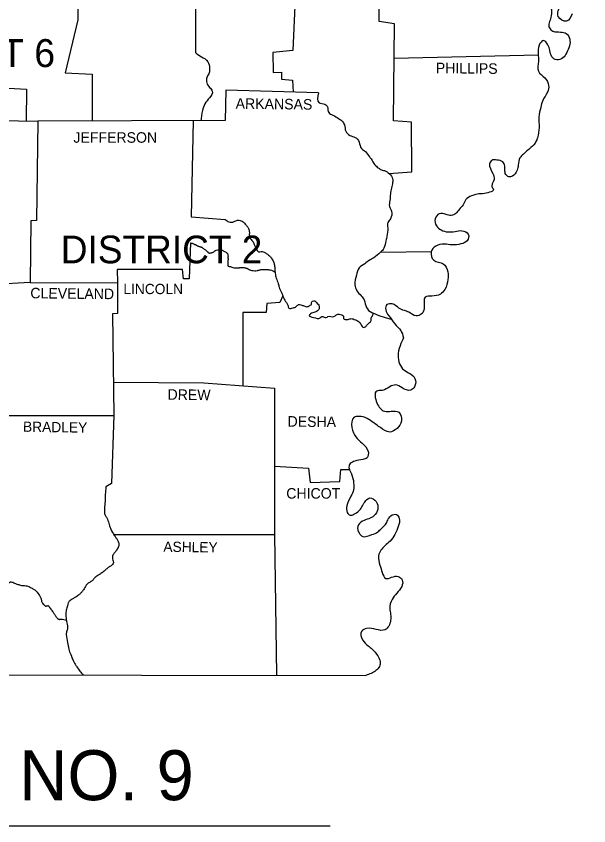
# Model space of a CAD drawing. Extents: x 6028647 to 6035072, y 5366486 to 5368495.
# Drawn here: x 6031362.3 to 6031596, y 5367756.8 to 5368087.3 of the extents above; entities that cross this region are included whole.
import ezdxf

# ---------------------------------------------------------------- set-up
doc = ezdxf.new("R2010")
doc.units = 0
doc.layers.add('Default', color=7, linetype='Continuous')

msp = doc.modelspace()

# ---------------------------------------------------------------- linework, layer by layer
at = {"layer": 'Default'}
for p, q in [((6031511.06, 5367990.98), (6031531.81, 5367991.29)), ((6031157.07, 5367756.79), (6031490.53, 5367756.79))]:
    msp.add_line(p, q, dxfattribs=at)
for points in [[(6031421.06, 5368129.07), (6031421.26, 5368111.17), (6031435.36, 5368110.87), (6031435.46, 5368072.47)], [(6031381.56, 5368124.47), (6031387.36, 5368124.07), (6031387.46, 5368085.87), (6031382.26, 5368064.17), (6031393.36, 5368063.67), (6031393.26, 5368044.56)], [(6031514.44, 5368023.17), (6031523.76, 5368023.77), (6031523.66, 5368044.07), (6031516.36, 5368044.57), (6031516.76, 5368084.27), (6031510.46, 5368085.17), (6031510.26, 5368111.87), (6031596.05, 5368112.47)], [(6031476.46, 5368100.77), (6031475.26, 5368073.37), (6031467.06, 5368072.47), (6031467.26, 5368064.37), (6031470.56, 5368064.47), (6031470.66, 5368061.67), (6031475.16, 5368061.17), (6031475.31, 5368056.35)], [(6031303.67, 5368099.52), (6031315.57, 5368098.77), (6031315.17, 5368086.27), (6031328.27, 5368085.77), (6031328.47, 5368074.87), (6031334.67, 5368074.37), (6031334.67, 5368072.47), (6031340.47, 5368072.07), (6031340.66, 5368065.07), (6031353.86, 5368065.07), (6031354.26, 5368058.17), (6031366.46, 5368057.57), (6031366.36, 5368044.55)], [(6031516.62, 5368070.16), (6031575.38, 5368071.62)], [(6031485.66, 5368056.07), (6031447.86, 5368057.07), (6031447.66, 5368044.77), (6031371.17, 5368044.47)], [(6031313.57, 5368031.27), (6031319.17, 5368032.07), (6031319.57, 5368035.47), (6031322.87, 5368036.07), (6031323.07, 5368038.07), (6031346.37, 5368038.77), (6031347.26, 5368044.87), (6031371.16, 5368044.47)], [(6031434.6, 5368044.72), (6031433.76, 5368005.47), (6031447.66, 5368004.37)], [(6031371.17, 5368044.47), (6031370.56, 5368003.87), (6031368.26, 5368003.77), (6031367.96, 5367978.67)], [(6031433.46, 5367994.77), (6031432.86, 5367980.07), (6031430.56, 5367980.07), (6031430.16, 5367983.97), (6031403.56, 5367983.97), (6031403.59, 5367978.47)], [(6031367.96, 5367978.67), (6031353.34, 5367977.77)], [(6031367.96, 5367978.67), (6031403.59, 5367978.47)], [(6031403.59, 5367978.47), (6031403.66, 5367965.97), (6031401.56, 5367965.87), (6031402.16, 5367924.37)], [(6031471.16, 5367973.17), (6031469.96, 5367970.47), (6031464.66, 5367969.97), (6031464.36, 5367966.37), (6031454.86, 5367966.37), (6031454.76, 5367936.47)], [(6031508.16, 5367966.07), (6031510.4, 5367965.19), (6031512.97, 5367964.3), (6031515.41, 5367963.68)], [(6031401.86, 5367937.97), (6031438.96, 5367937.67), (6031467.76, 5367935.47)], [(6031467.76, 5367935.47), (6031467.76, 5367875.67), (6031468.56, 5367818.23)], [(6031356.97, 5367924.27), (6031402.16, 5367924.37)], [(6031402.16, 5367924.37), (6031401.16, 5367896.57), (6031398.96, 5367895.17)], [(6031467.76, 5367903.6), (6031481.66, 5367902.77), (6031482.26, 5367896.97), (6031494.36, 5367897.37), (6031494.86, 5367902.27), (6031498.6, 5367902.27)], [(6031138.37, 5367899.67), (6031138.57, 5367818.77), (6031505.06, 5367818.17)], [(6031402.12, 5367875.77), (6031467.76, 5367875.77)]]:
    msp.add_lwpolyline(points, dxfattribs=at)
for points in [[(6031589.26, 5368088.27), (6031586.96, 5368085.37), (6031583.56, 5368087.17), (6031583.56, 5368089.57), (6031584.06, 5368092.07), (6031582.86, 5368093.67), (6031580.76, 5368092.97), (6031580.76, 5368089.87), (6031580.56, 5368086.87), (6031579.96, 5368082.57), (6031581.36, 5368081.27), (6031584.56, 5368080.87), (6031586.86, 5368080.27), (6031588.26, 5368077.97), (6031588.16, 5368075.17), (6031587.06, 5368072.47), (6031585.46, 5368070.27), (6031582.96, 5368069.47), (6031580.96, 5368070.77), (6031580.16, 5368073.37), (6031579.26, 5368075.67), (6031577.56, 5368077.37), (6031575.76, 5368075.47), (6031575.36, 5368071.97), (6031575.46, 5368068.97), (6031575.46, 5368064.87), (6031578.06, 5368062.17), (6031579.66, 5368059.07), (6031579.16, 5368056.27), (6031577.26, 5368052.97), (6031576.46, 5368050.07), (6031575.66, 5368046.17), (6031575.76, 5368041.87), (6031575.06, 5368037.67), (6031573.66, 5368034.87), (6031571.06, 5368032.57), (6031569.36, 5368031.07), (6031567.96, 5368029.57), (6031567.26, 5368026.57), (6031566.76, 5368024.47), (6031564.86, 5368021.97), (6031563.36, 5368021.77), (6031562.16, 5368022.77), (6031561.76, 5368024.47), (6031561.76, 5368026.17), (6031560.96, 5368027.87), (6031558.46, 5368028.57), (6031556.46, 5368028.47), (6031555.56, 5368027.07), (6031556.86, 5368023.17), (6031557.36, 5368020.67), (6031556.66, 5368017.27), (6031557.06, 5368016.87), (6031553.46, 5368014.97), (6031550.56, 5368014.67), (6031548.16, 5368013.97), (6031545.86, 5368012.47), (6031544.76, 5368010.27), (6031543.16, 5368008.47), (6031541.76, 5368006.77), (6031539.86, 5368005.97), (6031537.76, 5368006.37), (6031534.96, 5368006.67), (6031533.36, 5368004.67), (6031533.86, 5368001.77), (6031535.76, 5368000.07), (6031538.56, 5367999.27), (6031541.46, 5367999.47), (6031544.26, 5367999.77), (6031546.86, 5367998.37), (6031546.36, 5367995.67), (6031543.86, 5367994.37), (6031540.16, 5367993.97), (6031537.16, 5367994.27), (6031533.56, 5367993.47), (6031531.76, 5367991.17), (6031532.76, 5367987.67), (6031536.66, 5367986.27), (6031538.46, 5367982.97), (6031538.56, 5367979.87), (6031537.26, 5367975.77), (6031535.46, 5367973.87), (6031531.96, 5367973.07), (6031529.26, 5367972.57), (6031528.86, 5367967.97), (6031527.66, 5367965.67), (6031525.56, 5367964.97), (6031522.56, 5367966.47), (6031520.76, 5367967.17), (6031518.56, 5367968.17), (6031515.76, 5367969.87), (6031513.66, 5367969.57), (6031514.26, 5367965.17), (6031514.46, 5367964.97), (6031516.86, 5367961.67), (6031519.26, 5367959.07), (6031520.36, 5367955.97)], [(6031435.46, 5368072.47), (6031437.96, 5368070.77), (6031440.56, 5368068.77), (6031441.26, 5368066.07), (6031441.06, 5368064.17), (6031440.26, 5368062.57), (6031440.06, 5368060.07), (6031441.26, 5368058.27), (6031442.36, 5368056.77), (6031441.26, 5368054.07), (6031439.36, 5368051.57), (6031438.36, 5368048.77), (6031437.66, 5368044.57)], [(6031485.66, 5368056.07), (6031485.96, 5368051.97), (6031488.36, 5368051.37), (6031489.36, 5368050.27), (6031489.86, 5368047.97), (6031491.56, 5368046.97), (6031493.86, 5368045.57), (6031495.26, 5368044.57), (6031496.26, 5368042.97), (6031496.86, 5368040.37), (6031498.46, 5368038.67), (6031500.66, 5368037.87), (6031502.26, 5368035.97), (6031503.26, 5368033.27), (6031504.86, 5368032.07), (6031506.46, 5368029.97), (6031507.26, 5368029.07), (6031508.66, 5368026.67), (6031510.06, 5368025.47), (6031511.06, 5368024.77), (6031512.66, 5368024.27), (6031514.66, 5368022.97), (6031515.96, 5368020.97), (6031515.96, 5368019.47), (6031515.46, 5368017.17), (6031515.06, 5368014.77), (6031514.86, 5368012.07), (6031514.66, 5368009.67), (6031515.56, 5368007.67), (6031515.06, 5368004.67), (6031514.06, 5368003.07), (6031513.96, 5368000.87), (6031513.66, 5367997.57), (6031513.26, 5367995.67), (6031512.36, 5367992.57), (6031511.06, 5367990.97)], [(6031447.66, 5368004.37), (6031449.16, 5368003.37), (6031451.26, 5368003.47), (6031452.66, 5368004.07), (6031453.76, 5368003.97), (6031455.26, 5368003.07), (6031456.26, 5368001.87), (6031456.96, 5368000.97), (6031457.46, 5367999.57), (6031457.46, 5367998.27), (6031457.96, 5367996.47), (6031458.56, 5367995.77), (6031459.36, 5367994.47), (6031459.86, 5367993.27), (6031460.16, 5367992.47), (6031461.26, 5367991.17), (6031462.26, 5367991.27), (6031463.16, 5367991.17), (6031464.36, 5367990.47), (6031466.16, 5367989.07), (6031466.46, 5367988.67), (6031467.66, 5367986.07), (6031467.86, 5367984.47), (6031468.06, 5367982.37), (6031468.46, 5367980.37), (6031469.26, 5367978.17), (6031469.66, 5367976.67), (6031470.56, 5367974.57), (6031471.16, 5367973.17), (6031471.96, 5367971.37), (6031473.16, 5367969.37), (6031473.66, 5367968.17), (6031475.36, 5367968.27), (6031476.56, 5367968.77), (6031477.46, 5367969.57), (6031478.56, 5367969.47), (6031479.76, 5367969.07), (6031481.36, 5367968.77), (6031482.36, 5367969.37), (6031482.86, 5367969.77), (6031482.96, 5367970.67), (6031483.86, 5367971.17), (6031484.86, 5367970.47), (6031485.96, 5367968.87), (6031485.96, 5367967.87), (6031485.56, 5367967.27), (6031484.26, 5367966.47), (6031482.46, 5367965.87), (6031481.96, 5367965.17), (6031483.66, 5367964.37), (6031486.36, 5367964.17), (6031487.06, 5367964.77), (6031488.86, 5367964.27), (6031489.56, 5367964.77), (6031491.96, 5367964.67), (6031493.06, 5367965.47), (6031495.26, 5367965.37), (6031495.96, 5367964.87), (6031495.96, 5367963.97), (6031497.76, 5367963.57), (6031499.06, 5367963.87), (6031500.76, 5367963.37), (6031502.26, 5367962.57), (6031503.06, 5367961.47), (6031504.06, 5367960.27), (6031504.96, 5367960.57), (6031505.66, 5367961.47), (6031507.16, 5367963.07), (6031507.16, 5367964.07), (6031507.56, 5367964.77), (6031508.16, 5367966.07)], [(6031433.46, 5367994.77), (6031433.93, 5367994.67), (6031434.38, 5367994.54), (6031435.26, 5367994.17), (6031435.6, 5367994), (6031435.92, 5367993.82), (6031436.24, 5367993.64), (6031436.56, 5367993.47), (6031436.99, 5367993.31), (6031437.42, 5367993.19), (6031437.85, 5367993.06), (6031438.26, 5367992.87), (6031438.83, 5367992.49), (6031439.36, 5367992.07), (6031439.74, 5367991.75), (6031440.11, 5367991.41), (6031440.47, 5367991.07), (6031440.67, 5367990.92), (6031440.86, 5367990.77), (6031441.28, 5367990.63), (6031441.75, 5367990.66), (6031442.22, 5367990.8), (6031442.66, 5367990.97), (6031442.99, 5367991.16), (6031443.3, 5367991.39), (6031443.62, 5367991.61), (6031443.96, 5367991.77), (6031445.26, 5367991.97), (6031446.26, 5367991.87), (6031447.36, 5367991.27), (6031448.02, 5367990.9), (6031448.32, 5367990.68), (6031448.45, 5367990.54), (6031448.51, 5367990.46), (6031448.56, 5367990.37), (6031448.76, 5367989.73), (6031448.77, 5367989.4), (6031448.76, 5367989.07), (6031448.76, 5367987.57), (6031448.76, 5367985.47), (6031448.84, 5367985.33), (6031449.02, 5367985.25), (6031449.46, 5367985.17), (6031450.71, 5367984.79), (6031451.96, 5367984.57), (6031452.39, 5367984.58), (6031452.81, 5367984.61), (6031453.24, 5367984.65), (6031453.66, 5367984.67), (6031454.46, 5367984.69), (6031455.26, 5367984.67), (6031455.92, 5367984.57), (6031456.25, 5367984.48), (6031456.56, 5367984.37), (6031456.85, 5367984.23), (6031457.11, 5367984.06), (6031457.38, 5367983.9), (6031457.66, 5367983.77), (6031458.46, 5367983.57), (6031459.66, 5367983.37), (6031460.66, 5367983.47), (6031461.09, 5367983.58), (6031461.51, 5367983.71), (6031461.93, 5367983.82), (6031462.36, 5367983.87), (6031463.36, 5367983.87), (6031464.96, 5367983.87), (6031465.47, 5367983.84), (6031465.72, 5367983.81), (6031465.96, 5367983.77), (6031467.03, 5367983.37), (6031467.54, 5367983.07), (6031468.03, 5367982.74)], [(6031511.06, 5367990.97), (6031508.26, 5367988.67), (6031506.46, 5367987.67), (6031504.56, 5367986.27), (6031502.26, 5367984.57), (6031501.16, 5367981.67), (6031500.56, 5367977.67), (6031501.36, 5367975.27), (6031503.16, 5367973.17), (6031504.36, 5367971.47), (6031505.26, 5367968.47), (6031507.46, 5367966.37), (6031508.16, 5367966.07)], [(6031520.36, 5367955.97), (6031519.36, 5367953.67), (6031518.26, 5367949.67), (6031518.56, 5367946.27), (6031520.06, 5367943.37), (6031522.46, 5367941.77), (6031525.06, 5367939.47), (6031524.86, 5367935.97), (6031523.36, 5367934.67), (6031519.86, 5367935.57), (6031517.16, 5367936.77), (6031514.86, 5367936.07), (6031511.76, 5367934.57), (6031509.46, 5367934.27), (6031509.56, 5367929.47), (6031512.66, 5367926.07), (6031515.36, 5367926.07), (6031518.46, 5367925.67), (6031519.56, 5367922.07), (6031517.76, 5367919.07), (6031514.76, 5367917.57), (6031510.96, 5367919.37), (6031508.26, 5367921.27), (6031505.56, 5367923.07), (6031502.16, 5367923.97), (6031500.26, 5367923.57), (6031499.36, 5367919.37), (6031500.96, 5367915.57), (6031503.56, 5367912.97), (6031505.96, 5367909.57), (6031505.56, 5367907.07), (6031503.76, 5367906.37), (6031500.56, 5367905.67), (6031498.66, 5367904.67), (6031498.16, 5367903.87), (6031499.16, 5367900.47), (6031500.06, 5367896.77), (6031500.06, 5367893.97), (6031498.96, 5367891.37), (6031497.26, 5367887.37), (6031497.46, 5367884.77), (6031498.66, 5367883.57), (6031500.16, 5367883.97), (6031502.16, 5367885.37), (6031503.46, 5367886.97), (6031504.56, 5367888.97), (6031506.66, 5367890.67), (6031509.26, 5367889.17), (6031509.86, 5367886.07), (6031508.36, 5367883.37), (6031506.26, 5367882.17), (6031503.66, 5367881.17), (6031501.76, 5367878.97), (6031502.26, 5367876.37), (6031503.76, 5367874.97), (6031507.46, 5367875.67), (6031509.96, 5367876.77), (6031511.36, 5367878.17), (6031513.06, 5367879.87), (6031513.96, 5367881.57), (6031515.26, 5367883.37), (6031517.56, 5367883.87), (6031518.66, 5367882.37), (6031518.26, 5367878.97), (6031516.86, 5367875.77), (6031514.96, 5367873.07), (6031512.86, 5367871.17), (6031510.26, 5367867.07), (6031510.76, 5367863.27), (6031511.76, 5367860.17), (6031513.16, 5367857.77), (6031515.56, 5367858.27), (6031518.26, 5367858.57), (6031519.86, 5367857.27), (6031519.66, 5367854.47), (6031517.66, 5367851.77), (6031515.76, 5367849.17), (6031514.76, 5367845.57), (6031515.16, 5367843.07), (6031515.16, 5367840.77), (6031514.36, 5367838.27), (6031512.96, 5367836.87), (6031509.26, 5367836.97), (6031505.36, 5367837.37), (6031503.26, 5367836.17), (6031503.66, 5367832.77), (6031505.96, 5367830.27), (6031507.56, 5367828.97), (6031509.86, 5367826.17), (6031510.86, 5367823.87), (6031510.56, 5367821.87), (6031509.16, 5367820.17), (6031505.06, 5367818.17)], [(6031398.96, 5367895.17), (6031398.66, 5367892.07), (6031398.56, 5367889.17), (6031398.36, 5367886.37), (6031398.31, 5367885.32), (6031398.32, 5367884.8), (6031398.36, 5367884.27), (6031398.57, 5367883.66), (6031398.91, 5367883.11), (6031399.28, 5367882.56), (6031399.56, 5367881.97), (6031400.26, 5367879.77), (6031400.96, 5367877.87), (6031402.36, 5367875.37), (6031402.68, 5367874.89), (6031403.01, 5367874.43), (6031403.35, 5367873.96), (6031403.66, 5367873.47), (6031404.17, 5367872.13), (6031404.22, 5367871.43), (6031404.06, 5367870.77), (6031403.26, 5367869.37), (6031402.9, 5367868.84), (6031402.51, 5367868.32), (6031402.13, 5367867.8), (6031401.76, 5367867.27), (6031401.6, 5367866.36), (6031401.81, 5367865.31), (6031401.98, 5367864.3), (6031401.66, 5367863.47), (6031401.46, 5367863.29), (6031401.24, 5367863.13), (6031400.77, 5367862.85), (6031400.3, 5367862.58), (6031399.86, 5367862.27), (6031398.73, 5367861.25), (6031398.16, 5367860.75), (6031397.56, 5367860.27), (6031396.26, 5367859.37), (6031394.86, 5367858.47), (6031394.45, 5367858.12), (6031394.09, 5367857.7), (6031393.74, 5367857.27), (6031393.36, 5367856.87), (6031392.83, 5367856.48), (6031392.25, 5367856.14), (6031391.67, 5367855.8), (6031391.16, 5367855.37), (6031390.72, 5367854.79), (6031390.35, 5367854.14), (6031389.99, 5367853.48), (6031389.56, 5367852.87), (6031389.15, 5367852.36), (6031388.72, 5367851.86), (6031387.76, 5367850.97), (6031386.26, 5367849.97), (6031385.74, 5367849.65), (6031385.21, 5367849.35), (6031384.42, 5367848.86), (6031384.16, 5367848.67), (6031383.8, 5367848.26), (6031383.57, 5367847.77), (6031383.26, 5367846.67), (6031383, 5367845.75), (6031382.76, 5367844.83), (6031382.6, 5367843.9), (6031382.56, 5367842.97), (6031382.69, 5367841.62), (6031382.86, 5367840.27), (6031383.26, 5367837.87), (6031383.22, 5367837.12), (6031383.01, 5367836.37), (6031382.81, 5367835.62), (6031382.76, 5367834.87), (6031383.26, 5367831.57), (6031383.76, 5367828.97), (6031384.56, 5367826.67), (6031385.66, 5367824.07), (6031386.32, 5367822.85), (6031387.06, 5367821.67), (6031388.32, 5367819.97), (6031389.7, 5367818.36)], [(6031299.27, 5367872.07), (6031300.87, 5367873.17), (6031302.37, 5367873.77), (6031303.11, 5367873.64), (6031303.49, 5367873.55), (6031303.87, 5367873.47), (6031305.47, 5367873.27), (6031305.82, 5367873.29), (6031306.17, 5367873.36), (6031306.52, 5367873.43), (6031306.87, 5367873.47), (6031308.67, 5367873.17), (6031309.07, 5367872.97), (6031309.43, 5367872.73), (6031309.79, 5367872.49), (6031310.17, 5367872.27), (6031310.99, 5367871.82), (6031311.87, 5367871.57), (6031313.57, 5367871.57), (6031315.07, 5367871.57), (6031315.42, 5367871.45), (6031315.73, 5367871.16), (6031316.03, 5367870.85), (6031316.37, 5367870.67), (6031316.95, 5367870.59), (6031317.57, 5367870.57), (6031318.18, 5367870.62), (6031318.77, 5367870.77), (6031319.27, 5367870.97), (6031319.76, 5367871.18), (6031320.26, 5367871.38), (6031320.77, 5367871.57), (6031322.77, 5367872.17), (6031323.44, 5367872.37), (6031324.13, 5367872.55), (6031324.82, 5367872.62), (6031325.15, 5367872.58), (6031325.47, 5367872.47), (6031326.71, 5367871.7), (6031327.87, 5367870.77), (6031328.73, 5367870.09), (6031329.56, 5367869.37), (6031330.97, 5367867.77), (6031331.24, 5367867.34), (6031331.46, 5367866.88), (6031331.69, 5367866.41), (6031331.97, 5367865.97), (6031333.07, 5367864.97), (6031333.5, 5367864.75), (6031333.95, 5367864.56), (6031334.86, 5367864.27), (6031336.27, 5367863.97), (6031337.96, 5367863.47), (6031338.45, 5367863.34), (6031338.67, 5367863.24), (6031338.87, 5367863.07), (6031339.15, 5367862.62), (6031339.33, 5367862.14), (6031339.48, 5367861.65), (6031339.66, 5367861.17), (6031339.8, 5367860.84), (6031339.92, 5367860.51), (6031340.15, 5367859.86), (6031340.46, 5367859.21), (6031340.68, 5367858.89), (6031340.81, 5367858.73), (6031340.97, 5367858.57), (6031341.57, 5367858.07), (6031342.2, 5367857.75), (6031342.84, 5367857.61), (6031343.47, 5367857.67), (6031344.24, 5367857.94), (6031345.01, 5367858.27), (6031345.78, 5367858.6), (6031346.57, 5367858.87), (6031349.06, 5367859.57), (6031350.86, 5367860.17), (6031351.96, 5367860.57), (6031352.21, 5367860.62), (6031352.46, 5367860.63), (6031352.72, 5367860.63), (6031352.96, 5367860.67), (6031352.98, 5367860.69), (6031352.95, 5367860.71), (6031352.82, 5367860.77), (6031352.69, 5367860.82), (6031352.65, 5367860.85), (6031352.66, 5367860.87), (6031352.95, 5367861.01), (6031353.26, 5367861.12), (6031353.86, 5367861.17), (6031354.16, 5367861.06), (6031354.45, 5367860.88), (6031354.96, 5367860.37), (6031355.15, 5367860.1), (6031355.32, 5367859.82), (6031355.48, 5367859.54), (6031355.66, 5367859.27), (6031356.86, 5367857.67), (6031357.39, 5367856.97), (6031357.66, 5367856.62), (6031357.96, 5367856.27), (6031358.21, 5367856.07), (6031358.49, 5367855.92), (6031358.78, 5367855.83), (6031359.07, 5367855.77), (6031359.34, 5367855.86), (6031359.61, 5367856.1), (6031359.88, 5367856.32), (6031360.16, 5367856.37), (6031361.66, 5367855.87), (6031362.96, 5367855.37), (6031364.46, 5367854.97), (6031364.79, 5367854.93), (6031365.11, 5367854.92), (6031365.44, 5367854.9), (6031365.76, 5367854.87), (6031367.46, 5367854.47), (6031368.76, 5367853.77), (6031369.96, 5367853.07), (6031371.16, 5367851.77), (6031372.36, 5367849.77), (6031372.5, 5367849.39), (6031372.57, 5367848.98), (6031372.64, 5367848.57), (6031372.76, 5367848.17), (6031373.36, 5367847.28), (6031373.74, 5367846.91), (6031374.16, 5367846.57), (6031374.48, 5367846.51), (6031374.85, 5367846.61), (6031375.2, 5367846.68), (6031375.46, 5367846.57), (6031375.95, 5367845.93), (6031376.43, 5367845.28), (6031377.36, 5367843.97), (6031378.06, 5367842.97), (6031378.71, 5367842.01), (6031379.09, 5367841.56), (6031379.31, 5367841.36), (6031379.56, 5367841.17), (6031379.83, 5367841.09), (6031380.11, 5367841.11), (6031380.39, 5367841.17), (6031380.66, 5367841.17), (6031382.8, 5367840.76)]]:
    msp.add_spline(points, degree=3, dxfattribs=at)

# ---------------------------------------------------------------- texts
for s, height, p in [('DISTRICT 6', 11.4, (6031295.17, 5368066.57)), ('JEFFERSON', 4.3, (6031385.66, 5368035.67)), ('DISTRICT 2', 11.3, (6031380.51, 5367986.46)), ('LINCOLN', 4.2, (6031406.06, 5367973.87)), ('CHICOT', 4.3, (6031472.56, 5367890.37)), ('  ARK. HWY. DIST. NO. 9', 20.4, (6031121.03, 5367767.25))]:
    msp.add_text(s, height=height, dxfattribs=at).set_placement(p)
for s, height, rotation, p in [('PHILLIPS', 4.3, 359.3179, (6031533.56, 5368064.07)), ('ARKANSAS', 4.3, 359.2678, (6031451.86, 5368049.57)), ('CLEVELAND', 4.301, 359.3377, (6031368.06, 5367972.17)), ('DREW', 4.299, 359.2258, (6031424.06, 5367930.77)), ('DESHA', 4.299, 359.3704, (6031473.06, 5367919.77)), ('BRADLEY', 4.199, 359.1449, (6031365.06, 5367917.67)), ('ASHLEY', 4.201, 359.2361, (6031422.36, 5367868.67))]:
    msp.add_text(s, height=height, rotation=rotation, dxfattribs=at).set_placement(p)

doc.saveas('drawing.dxf')
